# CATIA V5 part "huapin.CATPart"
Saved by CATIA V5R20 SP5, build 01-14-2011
Part number: VASE
Material "Cloudy Sky"
Material "Light Green": density 7860 kg/m3, Young's modulus 2e+11 Pa, Poisson ratio 0.266
Material "Epoxy": density 1300 kg/m3, Young's modulus 3e+09 Pa, Poisson ratio 0.37, thermal expansion 6e-05 1/K
Material "Copper": density 8900 kg/m3, Young's modulus 1.1e+11 Pa, Poisson ratio 0.33, thermal expansion 1.65e-05 1/K
Bounding box of the stored display mesh (mm): x -40 to 40, y -40 to 59.343, z 0 to 112.994
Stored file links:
  E:\180212313\VASE.CATPart
  C:\Program Files\Dassault Systemes\B20\intel_a\startup\materials\Catalog.CATMaterial
  C:\Program Files\Dassault Systemes\B20\intel_a\startup\materials\brushed_metal2.jpg
  C:\Program Files\Dassault Systemes\B20\intel_a\startup\materials\red_env_512x512.jpg
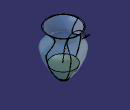
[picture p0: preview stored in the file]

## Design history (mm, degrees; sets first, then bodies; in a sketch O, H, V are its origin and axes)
Body1 (main body), material "Cloudy Sky"
  Plane1: type Offset, RefPlane xy-plane, Offset 20
  Plane2: type Offset, RefPlane Plane1, Offset 20
  Plane3: type Offset, RefPlane Plane2, Offset 20
  Plane4: type Offset, RefPlane Plane3, Offset 20
  Plane5: type Offset, RefPlane Plane4, Offset 20
  Sketch1 on Plane5, origin (0, 0, 100), H (1, 0, 0), V (0, 1, 0)
    circle A1 centre (0, 0) radius 35
    radius A1 = 35
  Sketch2 on Plane4, origin (0, 0, 80), H (1, 0, 0), V (0, 1, 0)
    circle A1 centre (0, 0) radius 20
    point P1 (20, 0)
    radius A1 = 20
    coincidence: A1 P1, P1 H
  Sketch3 on Plane3, origin (0, 0, 60), H (1, 0, 0), V (0, 1, 0)
    circle A1 centre (0, 0) radius 40
    radius A1 = 40
  Sketch4 on Plane2, origin (0, 0, 40), H (1, 0, 0), V (0, 1, 0)
    circle A1 centre (0, 0) radius 35
    radius A1 = 35
  Sketch5 on Plane1, origin (0, 0, 20), H (1, 0, 0), V (0, 1, 0)
    circle A1 centre (0, 0) radius 25
    radius A1 = 25
  Sketch6 on xy-plane, origin (0, 0, 0), H (1, 0, 0), V (0, 1, 0)
    circle A1 centre (0, 0) radius 10
    radius A1 = 10
  Loft1: solid, Sections (Sketch1; Sketch2; Sketch3; Sketch4; Sketch5; Sketch6)
  Shell1: ExtOffset 0, Face face of Loft1, IntOffset 1
  Sketch7 on yz-plane, origin (0, 0, 0), H (0, 1, 0), V (0, 0, 1)
    line L1 (0, 0) -> (10, 0)
    horizontal: L1 H
Body2, material "Light Green"
  Sketch8 on yz-plane, origin (0, 0, 0), H (0, 1, 0), V (0, 0, 1)
    point P1 (0, 28.5666)
    line L1 (0, 28.5666) -> (25.8471, 28.5666)
    point P2 (25.8471, 28.5666)
    spline S1 through (25.8471, 28.5666) (18.6544, 13.9546) (6.9833, 0)
    line L2 (6.9833, 0) -> (0, 0)
    line L3 (0, 0) -> (0, 28.5666)
    point P3 (6.9833, 0)
    point P4 (25.8471, 28.5666)
    point P5 (6.9833, 0)
    coincidence: P1 V, P4 P2, P5 H, P5 P3
    horizontal: L1 H, L2 H
    vertical: L3 V
  Shaft1: profile Sketch8, axis Z axis, angle 360
Body3, material "Copper"
  Sketch9 on yz-plane, origin (0, 0, 0), H (0, 1, 0), V (0, 0, 1)
    spline S1 through (-1.8593, 25.2839) (3.0263, 58.8372) (16.4615, 91.8494) (48.0819, 111.0614) (52.8317, 107.2731)
  Plane6: type Normal, Curve Sketch9, RefPoint vertex of Sketch9
  Sketch10 on Plane6, origin (0, -29.8732, 33.4816), H (1, 0, 0), V (0, 0.7462, 0.6658)
    circle A1 centre (0, 110.839) radius 0.7
    point P1 (0, 110.839)
    reference projected point E1 (0, 110.839) from vertex of Sketch9
    radius A1 = 0.7
    coincidence: P1 V, P1 E1
  Rib1: profile Sketch10, centre curve Sketch9
Body4, material "Epoxy"
  Sketch11 on Plane6, origin (0, -29.8732, 33.4816), H (1, 0, 0), V (0, 0.7462, 0.6658)
    spline S1 through (0, 104.3925) (-8.5033, 106.2866) (-3.6903, 115.8833) (7.8357, 117.5249) (7.8357, 106.2866) (0, 104.3925)
    point P1 (0, 104.3925)
    point P2 (0, 104.3925)
    coincidence: P1 V, P2 P1
  Pad1: profile Sketch11, direction (0, 0.6658, -0.7462), length 0.5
